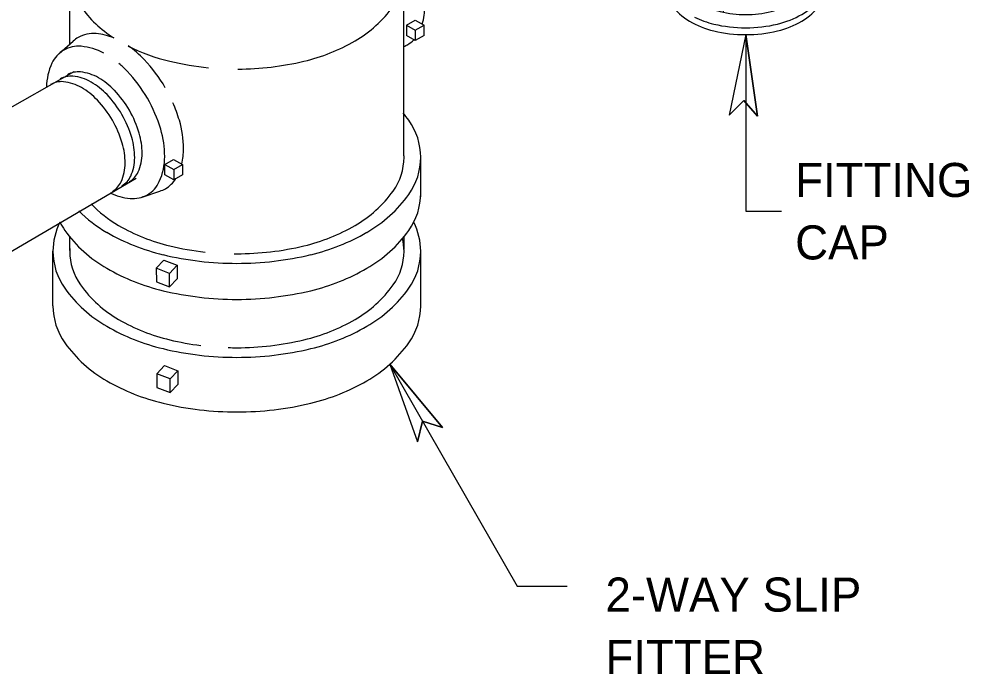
# Model space of a CAD drawing. Extents: x -224.9 to -217.6, y 224 to 234.
# Drawn here: x -219.59 to -217.918, y 228.218 to 229.372 of the extents above; entities that cross this region are included whole.
import ezdxf

# ---------------------------------------------------------------- set-up
doc = ezdxf.new("R2010")
doc.units = 0
for name, color, linetype in [('Default', 7, 'Continuous'), ('DETL-DIMS', 7, 'Continuous'), ('DETL-LINE', 7, 'Continuous'), ('DETL-NOTE', 7, 'Continuous')]:
    doc.layers.add(name, color=color, linetype=linetype)

# ---------------------------------------------------------------- blocks, each defined once
blk = doc.blocks.new('SE-0419')
at = {"layer": 'Default'}
for p, q in [((0.102, 0.1238), (0.102, 0.0684)), ((0.125, 0.1174), (0.125, 0.062)), ((0.1675, 0.1004), (0.1675, 0.0454)), ((0.1956, 0.085), (0.1956, 0.0299)), ((0.2274, 0.063), (0.2274, 0.0059)), ((0.2504, 0.0394), (0.2504, -0.0192)), ((-0.3251, -0.0845), (-0.3251, -0.0155)), ((0.3041, -0.0792), (0.3041, -0.0155)), ((-0.4042, -0.1396), (-0.4042, -0.1082)), ((-0.2972, -0.116), (-0.2985, -0.1024)), ((-0.2838, -0.1705), (-0.2972, -0.116)), ((-0.2838, -0.1209), (-0.2838, -0.1743)), ((-0.2557, -0.1894), (-0.2726, -0.1311)), ((0.3826, -0.1384), (0.3826, -0.1079)), ((-0.23, -0.1726), (-0.2312, -0.159)), ((-0.2196, -0.2125), (-0.23, -0.1726)), ((-0.2196, -0.1674), (-0.2196, -0.2125)), ((-0.2021, -0.1844), (-0.2031, -0.1734)), ((-0.1917, -0.2208), (-0.2021, -0.1844)), ((-0.1539, -0.199), (-0.1547, -0.1904)), ((-0.1435, -0.2354), (-0.1539, -0.199)), ((-0.1435, -0.1947), (-0.1435, -0.2376)), ((-0.1226, -0.1988), (-0.1226, -0.2555))]:
    blk.add_line(p, q, dxfattribs=at)
for centre, radius, start, end in [((-0.0515, -0.1807), 0.3598, 103.4495, 120), ((-0.0481, -0.1632), 0.3247, 103.4495, 120), ((-0.0087, -0.3594), 0.5435, 90, 103.4495), ((-0.0095, -0.3245), 0.4905, 90, 103.4495), ((-0.0095, -0.3245), 0.4905, 76.5505, 90), ((-0.0087, -0.3594), 0.5435, 76.5505, 90), ((0.0291, -0.1632), 0.3247, 60, 76.5505), ((0.034, -0.1807), 0.3598, 60, 76.5505), ((-0.1165, -0.068), 0.2297, 120, 144.3429), ((-0.1068, -0.0616), 0.2073, 120, 144.3429), ((-0.0118, -0.352), 0.4892, 76.5505, 76.6399), ((0.0267, -0.1912), 0.3238, 72.3249, 76.5505), ((0.0267, -0.1912), 0.3238, 60, 64.224), ((0.0877, -0.0616), 0.2073, 35.6571, 60), ((0.099, -0.068), 0.2297, 35.6571, 60), ((-0.2146, 0.0024), 0.1089, 144.3429, 180), ((-0.1953, 0.002), 0.0983, 144.3429, 180), ((-0.0485, -0.2471), 0.3238, 104.7234, 120), ((-0.0101, -0.408), 0.4892, 90, 98.4972), ((-0.0101, -0.408), 0.4892, 76.5505, 90), ((0.0284, -0.2471), 0.3238, 60, 76.5505), ((0.0852, -0.0898), 0.2067, 57.7051, 60), ((0.0915, -0.0929), 0.2067, 39.7861, 48.9139), ((0.1763, 0.002), 0.0983, 360, 35.6571), ((0.1972, 0.0024), 0.1089, 0, 35.6571), ((-0.1456, -0.1936), 0.2873, 126.9627, 144.3429), ((-0.2146, 0.0024), 0.1089, 180, 215.6571), ((-0.1953, 0.002), 0.0983, 180, 215.6571), ((-0.1071, -0.1458), 0.2067, 120, 144.3429), ((0.0869, -0.1458), 0.2067, 35.6571, 60), ((0.1763, 0.002), 0.0983, 324.3429, 0), ((0.1972, 0.0024), 0.1089, 324.3429, 360), ((0.124, -0.1936), 0.2873, 35.6571, 51.6971), ((-0.2683, -0.1055), 0.1362, 144.3429, 180), ((-0.1954, -0.0824), 0.098, 144.3429, 149.5093), ((0.1752, -0.0824), 0.098, 28.6517, 35.6571), ((0.2467, -0.1055), 0.1362, 0, 35.6571), ((-0.2164, -0.0854), 0.1089, 180, 215.6571), ((-0.1165, 0.0728), 0.2297, 215.6571, 240), ((-0.1068, 0.0655), 0.2073, 215.6571, 240), ((0.0877, 0.0655), 0.2073, 300, 324.3429), ((0.099, 0.0728), 0.2297, 300, 324.3429), ((0.1954, -0.0854), 0.1089, 324.3429, 0), ((-0.2683, -0.1055), 0.1362, 180, 215.6571), ((-0.2683, -0.1395), 0.1362, 180, 215.6571), ((-0.1182, 0.0395), 0.2297, 218.3319, 227.6821), ((-0.0515, 0.1854), 0.3598, 240, 256.5505), ((-0.0481, 0.1672), 0.3247, 240, 256.5505), ((0.0291, 0.1672), 0.3247, 283.4495, 300), ((0.034, 0.1854), 0.3598, 283.4495, 300), ((0.2467, -0.1055), 0.1362, 324.3429, 0), ((0.2467, -0.1395), 0.1362, 324.3429, 0), ((-0.1456, -0.0175), 0.2873, 215.6571, 229.2644), ((-0.1182, -0.015), 0.2297, 215.6571, 240), ((-0.0532, 0.1537), 0.3598, 240.3437, 245.3714), ((-0.0087, 0.3641), 0.5435, 256.5505, 270), ((-0.0095, 0.3285), 0.4905, 256.5505, 270), ((-0.0095, 0.3285), 0.4905, 270, 283.4495), ((-0.0087, 0.3641), 0.5435, 270, 283.4495), ((0.0973, -0.015), 0.2297, 300, 324.3429), ((0.124, -0.0175), 0.2873, 300, 324.3429), ((-0.1456, -0.0515), 0.2873, 215.6571, 240), ((-0.1182, -0.0054), 0.2297, 232.9768, 240), ((-0.0532, 0.1072), 0.3598, 240, 242.3044), ((-0.0532, 0.0976), 0.3598, 240, 256.5505), ((-0.0532, 0.1106), 0.3598, 247.2356, 255.3251), ((-0.0532, 0.1537), 0.3598, 253.6366, 256.5505), ((-0.0105, 0.3324), 0.5435, 256.5505, 258.095), ((0.0323, 0.0976), 0.3598, 283.4495, 300), ((0.124, -0.0515), 0.2873, 300, 324.3429), ((-0.0642, 0.1234), 0.4499, 243.5559, 256.5505), ((-0.0105, 0.2763), 0.5435, 256.5505, 270), ((-0.0105, 0.2763), 0.5435, 270, 283.4495), ((0.0427, 0.1234), 0.4499, 283.4495, 300), ((-0.0642, 0.0894), 0.4499, 240, 256.5505), ((-0.0108, 0.3468), 0.6797, 256.5505, 270), ((-0.0108, 0.3468), 0.6797, 270, 283.4495), ((0.0427, 0.0894), 0.4499, 283.4495, 300), ((-0.0108, 0.3128), 0.6797, 256.5505, 270), ((-0.0108, 0.3128), 0.6797, 270, 283.4495)]:
    blk.add_arc(centre, radius, start, end, dxfattribs=at)

msp = doc.modelspace()

# ---------------------------------------------------------------- linework, layer by layer
at = {"layer": 'DETL-DIMS'}
for p, q in [((-218.3111, 229.344), (-218.3404, 229.2018)), ((-218.3111, 229.344), (-218.29, 229.2003)), ((-218.3111, 229.344), (-218.3111, 229.0329)), ((-218.3145, 229.228), (-218.3404, 229.2018)), ((-218.29, 229.2003), (-218.3145, 229.228)), ((-218.3111, 229.0329), (-218.2483, 229.0329)), ((-218.9374, 228.7635), (-218.8446, 228.6518)), ((-218.9374, 228.7635), (-218.8885, 228.6268)), ((-218.9374, 228.7635), (-218.7133, 228.3721)), ((-218.88, 228.6627), (-218.8885, 228.6268)), ((-218.8446, 228.6518), (-218.88, 228.6627)), ((-218.7133, 228.3721), (-218.6252, 228.3721))]:
    msp.add_line(p, q, dxfattribs=at)
for points in [[(-218.29, 229.2003), (-218.3111, 229.344), (-218.3404, 229.2018), (-218.3145, 229.228)], [(-218.8446, 228.6518), (-218.9374, 228.7635), (-218.8885, 228.6268), (-218.88, 228.6627)]]:
    msp.add_lwpolyline(points, close=True, dxfattribs=at)
at = {"layer": 'DETL-LINE'}
for p, q in [((-219.501, 229.3272), (-219.501, 229.4476)), ((-218.9127, 229.1342), (-218.9127, 229.445)), ((-218.9083, 229.3605), (-218.8928, 229.3696)), ((-218.8928, 229.3696), (-218.8771, 229.3607)), ((-218.9083, 229.3605), (-218.8927, 229.3516)), ((-218.9083, 229.3605), (-218.9082, 229.3425)), ((-218.8927, 229.3516), (-218.8771, 229.3607)), ((-218.8927, 229.3516), (-218.8926, 229.3336)), ((-218.877, 229.3427), (-218.8771, 229.3607)), ((-219.5196, 229.3108), (-219.4949, 229.3327)), ((-218.8926, 229.3336), (-218.9082, 229.3425)), ((-218.877, 229.3427), (-218.8926, 229.3336)), ((-219.4936, 229.2786), (-220.172, 228.892)), ((-219.3336, 229.115), (-219.318, 229.1241)), ((-219.318, 229.1241), (-219.3024, 229.1152)), ((-219.3179, 229.1061), (-219.3024, 229.1152)), ((-219.3024, 229.1152), (-219.3023, 229.0972)), ((-218.8831, 229.0584), (-218.8831, 229.1278)), ((-219.3336, 229.115), (-219.3179, 229.1061)), ((-219.3335, 229.097), (-219.3336, 229.115)), ((-219.3179, 229.1061), (-219.3178, 229.0881)), ((-220.0637, 228.6924), (-219.3842, 229.0908)), ((-219.3178, 229.0881), (-219.3335, 229.097)), ((-219.3023, 229.0972), (-219.3178, 229.0881)), ((-219.3735, 229.0577), (-219.3422, 229.0682)), ((-219.5009, 228.9637), (-219.5009, 228.9884)), ((-218.9125, 228.9662), (-218.9125, 228.9878)), ((-219.5305, 228.8662), (-219.5305, 228.9623)), ((-218.8831, 228.8662), (-218.8831, 228.9623)), ((-219.3486, 228.9324), (-219.3351, 228.9466)), ((-219.3253, 228.9234), (-219.3486, 228.9324)), ((-219.3486, 228.9324), (-219.3485, 228.9083)), ((-219.3351, 228.9466), (-219.3117, 228.9377)), ((-219.3253, 228.9234), (-219.3117, 228.9377)), ((-219.3117, 228.9377), (-219.3116, 228.9136)), ((-219.3252, 228.8994), (-219.3253, 228.9234)), ((-219.3485, 228.9083), (-219.3252, 228.8994)), ((-219.3116, 228.9136), (-219.3252, 228.8994)), ((-219.2519, 228.8862), (-219.2519, 228.8862)), ((-219.3477, 228.7465), (-219.3341, 228.7608)), ((-219.3341, 228.7608), (-219.3108, 228.7518)), ((-219.3243, 228.7376), (-219.3108, 228.7518)), ((-219.3108, 228.7518), (-219.3106, 228.7278)), ((-219.3243, 228.7376), (-219.3477, 228.7465)), ((-219.3477, 228.7465), (-219.3475, 228.7225)), ((-219.3242, 228.7136), (-219.3243, 228.7376)), ((-219.3475, 228.7225), (-219.3242, 228.7136)), ((-219.3106, 228.7278), (-219.3242, 228.7136))]:
    msp.add_line(p, q, dxfattribs=at)
for centre, radius, start, end in [((-219.3075, 229.5189), 0.2147, 215.6571, 237.3569), ((-219.1061, 229.5189), 0.2147, 300, 324.3429), ((-218.9833, 229.3936), 0.1074, 343.2518, 360), ((-219.4596, 229.2928), 0.0532, 120, 131.4926), ((-219.4596, 229.2928), 0.0532, 84.3429, 120), ((-219.4655, 229.2341), 0.1122, 67.9324, 84.3429), ((-219.1668, 229.6241), 0.3363, 283.4495, 300), ((-218.9319, 229.3703), 0.0509, 300, 316.1787), ((-219.4859, 229.2727), 0.0509, 120, 155.6571), ((-219.4859, 229.2727), 0.0509, 84.3429, 120), ((-219.4914, 229.2165), 0.1074, 61.9986, 84.3429), ((-219.2467, 229.6241), 0.3363, 243.2271, 256.5505), ((-219.4972, 229.1791), 0.1757, 43.4495, 55.6439), ((-218.9319, 229.3703), 0.0509, 292.1155, 300), ((-219.5624, 229.1174), 0.2654, 30.0921, 43.4495), ((-219.4345, 229.2494), 0.1074, 155.6571, 178.6382), ((-219.5218, 229.1639), 0.1681, 43.4495, 50.2149), ((-219.2068, 229.7912), 0.508, 256.5505, 264.3721), ((-219.2068, 229.7912), 0.508, 270.2128, 283.4495), ((-219.499, 229.2332), 0.0376, 84.3429, 120), ((-219.4859, 229.2408), 0.0376, 84.3429, 120), ((-219.5031, 229.1917), 0.0793, 60, 84.3429), ((-219.49, 229.1993), 0.0793, 60, 84.3429), ((-219.5124, 229.1604), 0.1242, 43.4495, 60), ((-219.5842, 229.1048), 0.254, 30, 43.4495), ((-219.5158, 229.2235), 0.0376, 84.3429, 120), ((-219.5199, 229.182), 0.0793, 60, 84.3429), ((-219.5424, 229.1431), 0.1242, 43.4495, 60), ((-219.5255, 229.1528), 0.1242, 43.4495, 60), ((-219.5716, 229.1092), 0.1877, 30, 43.4495), ((-219.5585, 229.1168), 0.1877, 30, 43.4495), ((-219.5885, 229.0995), 0.1877, 30, 43.4495), ((-219.5842, 229.1048), 0.254, 16.5505, 30), ((-219.5624, 229.1174), 0.2654, 16.5505, 23.6908), ((-219.5716, 229.1092), 0.1877, 16.5505, 30), ((-219.5585, 229.1168), 0.1877, 16.5505, 30), ((-219.096, 229.0554), 0.2362, 35.6571, 39.7018), ((-219.5885, 229.0995), 0.1877, 16.5505, 30), ((-219.4763, 229.143), 0.1757, 360, 16.5505), ((-218.9951, 229.1278), 0.112, 0, 35.6571), ((-219.4977, 229.1348), 0.1242, 0, 16.5505), ((-219.5019, 229.1293), 0.1681, 360, 16.5505), ((-219.5276, 229.1175), 0.1242, 0, 16.5505), ((-219.5108, 229.1273), 0.1242, 0, 16.5505), ((-219.4528, 229.1348), 0.0793, 335.6571, 0), ((-219.4128, 229.143), 0.1122, 346.137, 0), ((-219.0143, 229.1278), 0.1018, 360, 3.6111), ((-219.4827, 229.1175), 0.0793, 335.6571, 360), ((-219.4659, 229.1273), 0.0793, 335.6571, 360), ((-219.4411, 229.1293), 0.1074, 335.6571, 360), ((-219.0143, 229.1278), 0.1018, 324.3429, 360), ((-218.9951, 229.1278), 0.112, 324.3429, 0), ((-219.4148, 229.1176), 0.0376, 300, 335.6571), ((-219.4447, 229.1003), 0.0376, 300, 335.6571), ((-219.4279, 229.1101), 0.0376, 300, 335.6571), ((-219.3897, 229.106), 0.0509, 300, 335.6571), ((-219.3591, 229.1186), 0.0532, 300, 327.7484), ((-219.3841, 229.1622), 0.1074, 244.5189, 264.3429), ((-219.3591, 229.1186), 0.0532, 288.5074, 300), ((-219.1061, 229.1936), 0.2147, 300, 324.3429), ((-219.3897, 229.106), 0.0509, 264.3429, 300), ((-219.096, 229.2002), 0.2362, 300, 324.3429), ((-218.9951, 229.0644), 0.112, 324.3429, 360), ((-219.3176, 229.2002), 0.2362, 224.8513, 240), ((-219.3075, 229.1936), 0.2147, 223.4114, 240), ((-219.4185, 228.9623), 0.112, 152.8788, 180), ((-219.4185, 229.0644), 0.112, 206.6016, 215.6571), ((-219.3176, 229.1368), 0.2362, 215.6571, 240), ((-219.2467, 229.2989), 0.3363, 240, 256.5505), ((-219.1668, 229.2989), 0.3363, 283.4495, 300), ((-219.096, 229.1368), 0.2362, 300, 324.3429), ((-218.9951, 228.9623), 0.112, 360, 27.1212), ((-219.2507, 229.316), 0.3699, 240, 256.5505), ((-219.1628, 229.316), 0.3699, 283.4495, 300), ((-219.0143, 228.9623), 0.1018, 360, 12.8696), ((-219.3992, 228.9623), 0.1018, 177.1827, 180), ((-219.2068, 229.4659), 0.508, 256.5505, 263.681), ((-219.2068, 229.4659), 0.508, 270, 283.4495), ((-219.4185, 228.9623), 0.112, 180, 215.6571), ((-219.3992, 228.9623), 0.1018, 180, 215.6571), ((-219.2068, 229.4998), 0.5588, 256.5505, 270), ((-219.2068, 229.4659), 0.508, 269.4429, 270), ((-219.2068, 229.4998), 0.5588, 270, 283.4495), ((-219.0143, 228.9623), 0.1018, 324.3429, 360), ((-218.9951, 228.9623), 0.112, 324.3429, 360), ((-219.2507, 229.2526), 0.3699, 240, 256.5505), ((-219.1628, 229.2526), 0.3699, 283.4495, 300), ((-219.3075, 229.0281), 0.2147, 215.6571, 240), ((-219.1061, 229.0281), 0.2147, 300, 324.3429), ((-219.3176, 229.0347), 0.2362, 215.6571, 240), ((-219.2068, 229.4363), 0.5588, 256.5505, 270), ((-219.2068, 229.4363), 0.5588, 270, 283.4495), ((-219.096, 229.0347), 0.2362, 300, 324.3429), ((-219.4185, 228.8662), 0.112, 180, 215.6571), ((-218.9951, 228.8662), 0.112, 324.3429, 0), ((-219.2467, 229.1334), 0.3363, 240, 256.5505), ((-219.1668, 229.1334), 0.3363, 283.4495, 300), ((-219.2507, 229.1505), 0.3699, 240, 256.5505), ((-219.1628, 229.1505), 0.3699, 283.4495, 300), ((-219.3176, 228.9386), 0.2362, 215.6571, 240), ((-219.2068, 229.3004), 0.508, 256.5505, 262.8104), ((-219.2068, 229.3004), 0.508, 270, 283.4495), ((-219.096, 228.9386), 0.2362, 300, 324.3429), ((-219.2068, 229.3342), 0.5588, 256.5505, 270), ((-219.2068, 229.3004), 0.508, 268.2962, 270), ((-219.2068, 229.3342), 0.5588, 270, 283.4495), ((-219.2507, 229.0544), 0.3699, 240, 256.5505), ((-219.1628, 229.0544), 0.3699, 283.4495, 300), ((-219.2068, 229.2381), 0.5588, 256.5505, 270), ((-219.2068, 229.2381), 0.5588, 270, 283.4495)]:
    msp.add_arc(centre, radius, start, end, dxfattribs=at)

# ---------------------------------------------------------------- block references
at = {"layer": 'DETL-LINE', "xscale": 0.35502205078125, "yscale": 0.35502205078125}
msp.add_blockref('SE-0419', (-218.3073, 229.4742), dxfattribs=at)

# ---------------------------------------------------------------- texts
at = {"layer": 'DETL-NOTE'}
for s, p in [('FITTING', (-218.224, 229.0579)), ('CAP', (-218.224, 228.9479)), ('2-WAY SLIP ', (-218.5579, 228.3275)), ('FITTER', (-218.5579, 228.2175))]:
    msp.add_text(s, height=0.06, dxfattribs=at).set_placement(p)

doc.saveas('drawing.dxf')
